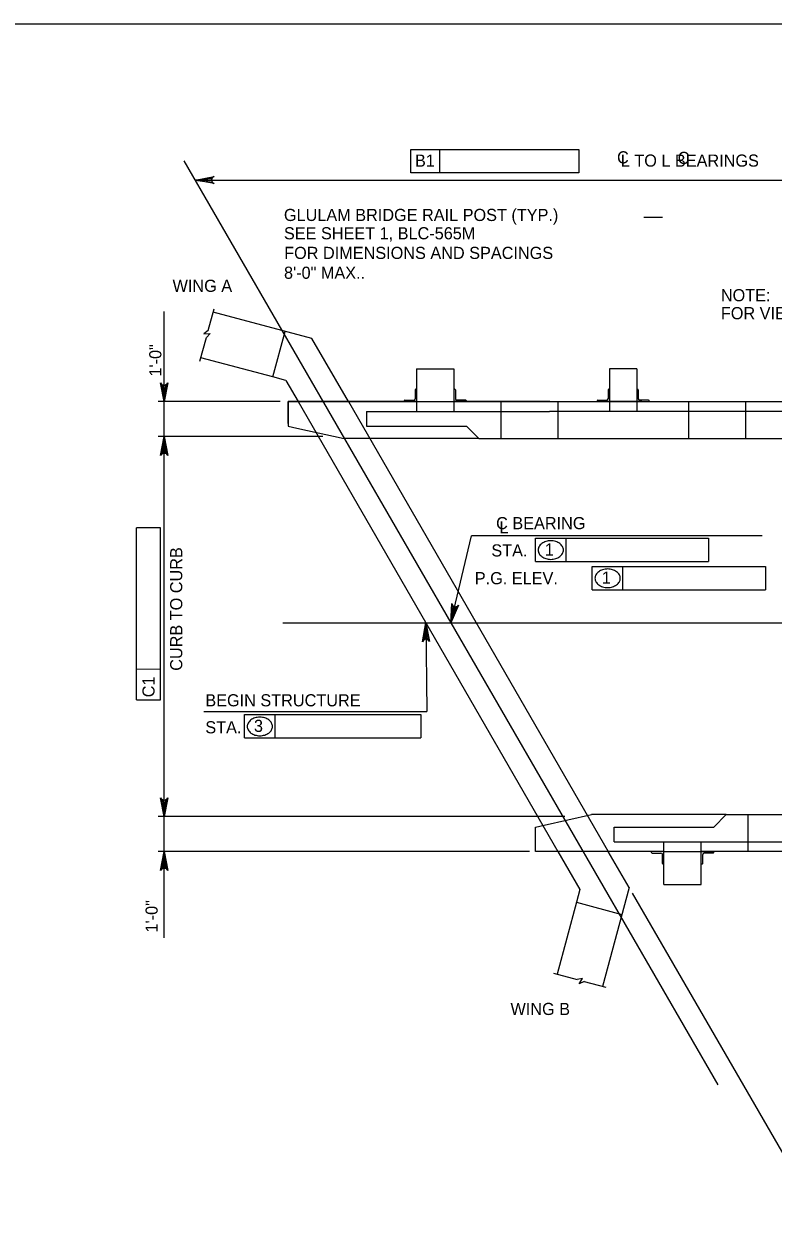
# Model space of a CAD drawing. Extents: x 638268 to 640277, y 295465 to 298435.
# Drawn here: x 638478.1 to 638663, y 296936.4 to 297232.5 of the extents above; entities that cross this region are included whole.
import ezdxf

# ---------------------------------------------------------------- set-up
doc = ezdxf.new("R2010")
doc.units = 0
for name, color, linetype in [('2', 7, 'Continuous'), ('3', 7, 'Continuous'), ('4', 7, 'Continuous')]:
    doc.layers.add(name, color=color, linetype=linetype)

msp = doc.modelspace()

# ---------------------------------------------------------------- linework, layer by layer
at = {"layer": '2'}
for p, q in [((638475.46, 297232.46), (639261.46, 297232.46)), ((638549.18, 297154.71), (638524.78, 297161.24)), ((638539.56, 297145.23), (638542.57, 297156.48)), ((638558.17, 297139.14), (638549.18, 297154.71)), ((638539.56, 297145.23), (638521.77, 297150)), ((638575.01, 297147.23), (638584.25, 297147.23)), ((638575.01, 297147.23), (638575.01, 297136.74)), ((638584.25, 297147.23), (638584.25, 297136.74)), ((638622.68, 297147.23), (638622.68, 297136.74)), ((638629.4, 297147.23), (638622.68, 297147.23)), ((638629.4, 297147.23), (638622.68, 297147.23)), ((638629.4, 297147.23), (638629.4, 297136.74)), ((638542.71, 297144.39), (638539.56, 297145.23)), ((638542.71, 297144.39), (638545.74, 297139.14)), ((638574.65, 297142.05), (638574.65, 297139.86)), ((638574.83, 297142.23), (638575.01, 297142.23)), ((638575.01, 297142.23), (638575.01, 297139.14)), ((638584.43, 297142.23), (638584.25, 297142.23)), ((638584.25, 297142.23), (638584.25, 297139.14)), ((638584.61, 297142.05), (638584.61, 297139.86)), ((638622.31, 297142.05), (638622.31, 297139.86)), ((638622.5, 297142.23), (638622.68, 297142.23)), ((638622.68, 297142.23), (638622.68, 297139.14)), ((638629.59, 297142.23), (638629.4, 297142.23)), ((638629.4, 297142.23), (638629.4, 297139.14)), ((638629.77, 297142.05), (638629.77, 297139.86)), ((638543.27, 297133.75), (638543.27, 297139.14)), ((638543.27, 297139.14), (638755.15, 297139.14)), ((638575.01, 297139.14), (638543.27, 297139.14)), ((638543.27, 297139.14), (638543.27, 297133.11)), ((638545.74, 297139.14), (638609.93, 297027.96)), ((638558.17, 297139.14), (638622.36, 297027.96)), ((638571.92, 297139.32), (638571.92, 297139.14)), ((638575.01, 297139.14), (638571.92, 297139.14)), ((638572.1, 297139.5), (638574.29, 297139.5)), ((638575.01, 297139.14), (638584.25, 297139.14)), ((638584.25, 297139.14), (638587.34, 297139.14)), ((638607.96, 297139.14), (638584.25, 297139.14)), ((638587.16, 297139.5), (638584.98, 297139.5)), ((638587.34, 297139.32), (638587.34, 297139.14)), ((638595.8, 297139.14), (638595.8, 297130.02)), ((638608.04, 297139.14), (638755.13, 297139.14)), ((638609.87, 297139.14), (638609.87, 297130.02)), ((638619.59, 297139.32), (638619.59, 297139.14)), ((638622.68, 297139.14), (638619.59, 297139.14)), ((638619.77, 297139.5), (638621.95, 297139.5)), ((638630.66, 297139.14), (638621.42, 297139.14)), ((638629.4, 297139.14), (638622.68, 297139.14)), ((638629.4, 297139.14), (638632.5, 297139.14)), ((638632.31, 297139.5), (638630.13, 297139.5)), ((638632.5, 297139.32), (638632.5, 297139.14)), ((638642.21, 297139.14), (638642.21, 297130.02)), ((638656.23, 297139.14), (638656.24, 297130.02)), ((638562.69, 297136.74), (638607.87, 297136.74)), ((638562.69, 297136.74), (638562.69, 297133.11)), ((638735.71, 297136.74), (638607.87, 297136.74)), ((638543.27, 297133.11), (638545.44, 297132.62)), ((638545.44, 297132.62), (638557.12, 297130.02)), ((638562.69, 297133.11), (638587.33, 297133.11)), ((638590.42, 297130.02), (638587.33, 297133.11)), ((638590.42, 297130.02), (638557.12, 297130.02)), ((638590.42, 297130.02), (638606.58, 297130.02)), ((638590.42, 297130.02), (638741.28, 297130.02)), ((638604.36, 297033.99), (638606.53, 297034.48)), ((638606.53, 297034.48), (638618.21, 297037.09)), ((638651.51, 297037.09), (638618.21, 297037.09)), ((638651.51, 297037.09), (638648.42, 297033.99)), ((638651.51, 297037.09), (638667.67, 297037.09)), ((638651.51, 297037.09), (638802.37, 297037.09)), ((638656.89, 297027.96), (638656.89, 297037.09)), ((638604.36, 297027.96), (638604.36, 297033.99)), ((638623.78, 297033.99), (638648.42, 297033.99)), ((638623.78, 297030.36), (638623.78, 297033.99)), ((638623.78, 297030.36), (638668.96, 297030.36)), ((638636.1, 297019.87), (638636.1, 297030.36)), ((638645.34, 297019.87), (638645.34, 297030.36)), ((638636.1, 297027.96), (638604.36, 297027.96)), ((638609.93, 297027.96), (638615.33, 297018.61)), ((638627.5, 297019.06), (638622.36, 297027.96)), ((638633.01, 297027.78), (638633.01, 297027.96)), ((638636.1, 297027.96), (638633.01, 297027.96)), ((638633.19, 297027.6), (638635.38, 297027.6)), ((638635.74, 297025.06), (638635.74, 297027.24)), ((638636.1, 297027.96), (638645.34, 297027.96)), ((638636.1, 297024.87), (638636.1, 297027.96)), ((638645.34, 297027.96), (638648.43, 297027.96)), ((638669.05, 297027.96), (638645.34, 297027.96)), ((638645.34, 297024.87), (638645.34, 297027.96)), ((638645.7, 297025.06), (638645.7, 297027.24)), ((638648.25, 297027.6), (638646.07, 297027.6)), ((638648.43, 297027.78), (638648.43, 297027.96)), ((638635.92, 297024.87), (638636.1, 297024.87)), ((638645.52, 297024.87), (638645.34, 297024.87)), ((638636.1, 297019.87), (638645.34, 297019.87)), ((638615.33, 297018.61), (638614.48, 297015.46)), ((638627.5, 297019.06), (638620.96, 296994.66)), ((638614.48, 297015.46), (638609.71, 296997.67)), ((638614.48, 297015.46), (638625.72, 297012.45))]:
    msp.add_line(p, q, dxfattribs=at)
for centre, radius, start, end in [((638574.83, 297142.05), 0.182, 90, 179.9984), ((638584.43, 297142.05), 0.182, 0.0016, 90), ((638622.5, 297142.05), 0.182, 90, 179.9984), ((638629.59, 297142.05), 0.182, 0.0016, 90), ((638572.1, 297139.32), 0.182, 90, 179.9984), ((638574.29, 297139.86), 0.364, 270, 359.9984), ((638584.98, 297139.86), 0.364, 180.0016, 270), ((638587.16, 297139.32), 0.182, 0.0016, 90), ((638619.77, 297139.32), 0.182, 90, 179.9984), ((638621.95, 297139.86), 0.364, 270, 359.9984), ((638630.13, 297139.86), 0.364, 180.0016, 270), ((638632.31, 297139.32), 0.182, 0.0016, 90), ((638633.19, 297027.78), 0.182, 180.0016, 270), ((638635.38, 297027.24), 0.364, 0.0016, 90), ((638646.07, 297027.24), 0.364, 90, 179.9984), ((638648.25, 297027.78), 0.182, 270, 359.9984), ((638635.92, 297025.06), 0.182, 180.0016, 270), ((638645.52, 297025.06), 0.182, 270, 359.9984)]:
    msp.add_arc(centre, radius, start, end, dxfattribs=at)
at = {"layer": '3'}
for p, q in [((638517.58, 297198.67), (638649.41, 296970.33)), ((638523.56, 297156.7), (638524.99, 297162.04)), ((638523.56, 297156.7), (638522.47, 297155.88)), ((638522.47, 297155.88), (638524.02, 297155.98)), ((638524.02, 297155.98), (638523.1, 297154.96)), ((638521.53, 297149.13), (638523.1, 297154.96)), ((638608.85, 296997.9), (638614.68, 296996.34)), ((638616.02, 296996.64), (638614.68, 296996.34)), ((638615.16, 296995.33), (638616.02, 296996.64)), ((638616.42, 296995.87), (638615.16, 296995.33)), ((638616.42, 296995.87), (638621.75, 296994.44))]:
    msp.add_line(p, q, dxfattribs=at)
msp.add_lwpolyline([(638523.29, 297194.39), (638523.29, 297193.4), (638520.34, 297193.9)], close=True, dxfattribs=at)
at = {"layer": '4'}
for p, q in [((638573.56, 297201.44), (638580.79, 297201.44)), ((638573.56, 297195.67), (638573.56, 297201.44)), ((638580.79, 297195.67), (638580.79, 297201.44)), ((638580.79, 297201.44), (638615.08, 297201.44)), ((638615.08, 297201.44), (638615.08, 297195.67)), ((638615.08, 297195.67), (638573.56, 297195.67)), ((638520.34, 297193.9), (638711.75, 297193.9)), ((638631.15, 297184.76), (638635.78, 297184.76)), ((638512.67, 297006.68), (638512.67, 297161.41)), ((638541.29, 297139.14), (638511.23, 297139.14)), ((638551.87, 297130.49), (638511.23, 297130.49)), ((638511.77, 297107.95), (638505.86, 297107.96)), ((638505.86, 297073), (638505.86, 297107.96)), ((638511.77, 297065.43), (638511.77, 297107.95)), ((638583.5, 297084.5), (638588.55, 297106.01)), ((638660.36, 297106.01), (638588.55, 297106.01)), ((638604.37, 297105.4), (638611.95, 297105.4)), ((638604.37, 297099.63), (638604.37, 297105.4)), ((638611.95, 297099.63), (638611.95, 297105.4)), ((638611.95, 297105.4), (638647.13, 297105.4)), ((638647.13, 297105.4), (638647.13, 297099.63)), ((638604.37, 297099.63), (638647.13, 297099.63)), ((638618.42, 297098.43), (638625.99, 297098.43)), ((638618.42, 297092.66), (638618.42, 297098.43)), ((638625.99, 297092.66), (638625.99, 297098.43)), ((638625.99, 297098.43), (638661.18, 297098.43)), ((638661.18, 297098.43), (638661.18, 297092.66)), ((638618.42, 297092.66), (638661.18, 297092.66)), ((638541.99, 297084.5), (638827.01, 297084.5)), ((638577.28, 297084.5), (638577.55, 297062.57)), ((638505.86, 297065.44), (638505.86, 297073)), ((638511.77, 297072.99), (638505.86, 297073)), ((638505.86, 297065.44), (638511.77, 297065.43)), ((638522.47, 297062.57), (638577.55, 297062.57)), ((638532.52, 297056.04), (638532.52, 297061.81)), ((638532.52, 297061.81), (638540.1, 297061.81)), ((638540.1, 297056.04), (638540.1, 297061.81)), ((638540.1, 297061.81), (638576.11, 297061.81)), ((638576.11, 297061.81), (638576.11, 297056.04)), ((638532.52, 297056.04), (638576.11, 297056.04)), ((638611.65, 297036.61), (638511.23, 297036.61)), ((638602.93, 297027.96), (638511.23, 297027.96)), ((638628.28, 297017.71), (638675.2, 296936.44))]:
    msp.add_line(p, q, dxfattribs=at)
for points in [[(638520.34, 297193.9), (638525, 297194.77), (638524.64, 297194.52), (638524.46, 297194.21), (638524.4, 297193.9), (638524.46, 297193.58), (638524.64, 297193.27), (638525, 297193.02), (638520.34, 297193.9), (638524.64, 297193.27), (638524.46, 297193.58), (638520.34, 297193.9), (638524.4, 297193.9), (638524.46, 297194.21), (638520.34, 297193.9), (638524.64, 297194.52)], [(638512.67, 297139.14), (638511.8, 297143.8), (638512.05, 297143.44), (638512.36, 297143.25), (638512.67, 297143.2), (638512.98, 297143.25), (638513.3, 297143.44), (638513.55, 297143.8), (638512.67, 297139.14), (638513.3, 297143.44), (638512.98, 297143.25), (638512.67, 297139.14), (638512.67, 297143.2), (638512.36, 297143.25), (638512.67, 297139.14), (638512.05, 297143.44)], [(638512.67, 297130.49), (638513.55, 297125.82), (638513.3, 297126.18), (638512.98, 297126.37), (638512.67, 297126.42), (638512.36, 297126.37), (638512.05, 297126.18), (638511.8, 297125.82), (638512.67, 297130.49), (638512.05, 297126.18), (638512.36, 297126.37), (638512.67, 297130.49), (638512.67, 297126.42), (638512.98, 297126.37), (638512.67, 297130.49), (638513.3, 297126.18)], [(638583.5, 297084.5), (638583.71, 297089.24), (638583.87, 297088.84), (638584.13, 297088.58), (638584.43, 297088.46), (638584.74, 297088.44), (638585.09, 297088.55), (638585.41, 297088.84), (638583.5, 297084.5), (638585.09, 297088.55), (638584.74, 297088.44), (638583.5, 297084.5), (638584.43, 297088.46), (638584.13, 297088.58), (638583.5, 297084.5), (638583.87, 297088.84)], [(638577.28, 297084.5), (638578.21, 297079.85), (638577.96, 297080.21), (638577.65, 297080.39), (638577.33, 297080.44), (638577.02, 297080.39), (638576.71, 297080.2), (638576.47, 297079.83), (638577.28, 297084.5), (638576.71, 297080.2), (638577.02, 297080.39), (638577.28, 297084.5), (638577.33, 297080.44), (638577.65, 297080.39), (638577.28, 297084.5), (638577.96, 297080.21)], [(638512.67, 297036.61), (638511.8, 297041.27), (638512.05, 297040.91), (638512.36, 297040.73), (638512.67, 297040.67), (638512.98, 297040.73), (638513.3, 297040.91), (638513.55, 297041.27), (638512.67, 297036.61), (638513.3, 297040.91), (638512.98, 297040.73), (638512.67, 297036.61), (638512.67, 297040.67), (638512.36, 297040.73), (638512.67, 297036.61), (638512.05, 297040.91)], [(638512.67, 297027.96), (638513.55, 297023.3), (638513.3, 297023.66), (638512.98, 297023.85), (638512.67, 297023.9), (638512.36, 297023.85), (638512.05, 297023.66), (638511.8, 297023.3), (638512.67, 297027.96), (638512.05, 297023.66), (638512.36, 297023.85), (638512.67, 297027.96), (638512.67, 297023.9), (638512.98, 297023.85), (638512.67, 297027.96), (638513.3, 297023.66)]]:
    msp.add_lwpolyline(points, dxfattribs=at)
for points in [[(638512.19, 297142.02), (638513.15, 297142.02), (638512.67, 297139.14)], [(638512.19, 297127.6), (638513.15, 297127.6), (638512.67, 297130.49)], [(638512.19, 297039.5), (638513.15, 297039.5), (638512.67, 297036.61)], [(638512.19, 297025.08), (638513.15, 297025.08), (638512.67, 297027.96)]]:
    msp.add_lwpolyline(points, close=True, dxfattribs=at)
for centre, radius, start, end in [((638606.75, 297102.47), 1.71, 150.6308, 180), ((638607.43, 297102.09), 2.49, 126.3544, 150.6308), ((638607.87, 297101.49), 3.23, 106.9552, 126.3544), ((638608.16, 297100.54), 4.22, 90, 106.9552), ((638608.16, 297100.54), 4.22, 73.0448, 90), ((638608.45, 297101.49), 3.23, 53.6456, 73.0448), ((638608.89, 297102.09), 2.49, 29.3692, 53.6456), ((638609.57, 297102.47), 1.71, 0, 29.3692), ((638606.75, 297102.47), 1.71, 180, 209.3692), ((638607.43, 297102.85), 2.49, 209.3692, 233.6456), ((638607.87, 297103.45), 3.23, 233.6456, 253.0448), ((638608.16, 297104.39), 4.22, 253.0448, 270), ((638608.16, 297104.39), 4.22, 270, 286.9552), ((638608.45, 297103.45), 3.23, 286.9552, 306.3544), ((638608.89, 297102.85), 2.49, 306.3544, 330.6308), ((638609.57, 297102.47), 1.71, 330.6308, 0), ((638621.47, 297095.12), 2.49, 126.3544, 150.6308), ((638621.91, 297094.52), 3.23, 106.9552, 126.3544), ((638622.2, 297093.57), 4.22, 90, 106.9552), ((638622.2, 297093.57), 4.22, 73.0448, 90), ((638622.49, 297094.52), 3.23, 53.6456, 73.0448), ((638622.93, 297095.12), 2.49, 29.3692, 53.6456), ((638620.79, 297095.5), 1.71, 150.6308, 180), ((638620.79, 297095.5), 1.71, 180, 209.3692), ((638621.47, 297095.88), 2.49, 209.3692, 233.6456), ((638621.91, 297096.48), 3.23, 233.6456, 253.0448), ((638622.49, 297096.48), 3.23, 286.9552, 306.3544), ((638622.93, 297095.88), 2.49, 306.3544, 330.6308), ((638623.61, 297095.5), 1.71, 0, 29.3692), ((638623.61, 297095.5), 1.71, 330.6308, 0), ((638622.2, 297097.43), 4.22, 253.0448, 270), ((638622.2, 297097.43), 4.22, 270, 286.9552), ((638536.31, 297056.95), 4.22, 90, 106.9552), ((638536.31, 297056.95), 4.22, 73.0448, 90), ((638534.9, 297058.88), 1.71, 150.6308, 180), ((638534.9, 297058.88), 1.71, 180, 209.3692), ((638535.58, 297058.5), 2.49, 126.3544, 150.6308), ((638536.02, 297057.9), 3.23, 106.9552, 126.3544), ((638536.6, 297057.9), 3.23, 53.6456, 73.0448), ((638537.04, 297058.5), 2.49, 29.3692, 53.6456), ((638537.71, 297058.88), 1.71, 0, 29.3692), ((638537.71, 297058.88), 1.71, 330.6308, 0), ((638535.58, 297059.26), 2.49, 209.3692, 233.6456), ((638536.02, 297059.86), 3.23, 233.6456, 253.0448), ((638536.31, 297060.81), 4.22, 253.0448, 270), ((638536.31, 297060.81), 4.22, 270, 286.9552), ((638536.6, 297059.86), 3.23, 286.9552, 306.3544), ((638537.04, 297059.26), 2.49, 306.3544, 330.6308)]:
    msp.add_arc(centre, radius, start, end, dxfattribs=at)

# ---------------------------------------------------------------- texts
for s, p in [('C', (638624.53, 297198)), ('L TO L BEARINGS', (638625.45, 297197.2)), ('C', (638639.5, 297197.86)), ('B1', (638574.63, 297197.2)), ('GLULAM BRIDGE RAIL POST (TYP.)', (638542.26, 297183.77)), ('SEE SHEET 1, BLC-565M', (638542.26, 297179.24)), ('FOR DIMENSIONS AND SPACINGS', (638542.32, 297174.39)), ('8\'-0" MAX..', (638542.28, 297169.49)), ('WING A', (638514.76, 297166.26)), ('NOTE:', (638650.17, 297163.94)), ('FOR VIEW B-B SEE SHEET 4.', (638650.17, 297159.5)), ('C BEARING', (638594.66, 297107.62)), ('L', (638595.48, 297106.57)), ('STA.', (638593.49, 297100.88)), ('1', (638606.71, 297101.12)), ('P.G. ELEV.', (638589.4, 297094.02)), ('1', (638620.75, 297094.15)), ('BEGIN STRUCTURE', (638522.85, 297063.85)), ('STA.', (638522.85, 297057.18)), ('3', (638534.86, 297057.53)), ('WING B', (638598.21, 296987.59))]:
    msp.add_text(s, height=3, dxfattribs=at).set_placement(p)
for s, rotation, p in [('1\'-0"', 90, (638511.99, 297145.35)), ('CURB TO CURB', 90, (638517.16, 297072.64)), ('C1', 89.9382, (638510.31, 297066.09)), ('1\'-0"', 90, (638511.08, 297007.99))]:
    msp.add_text(s, height=3, rotation=rotation, dxfattribs=at).set_placement(p)

doc.saveas('drawing.dxf')
